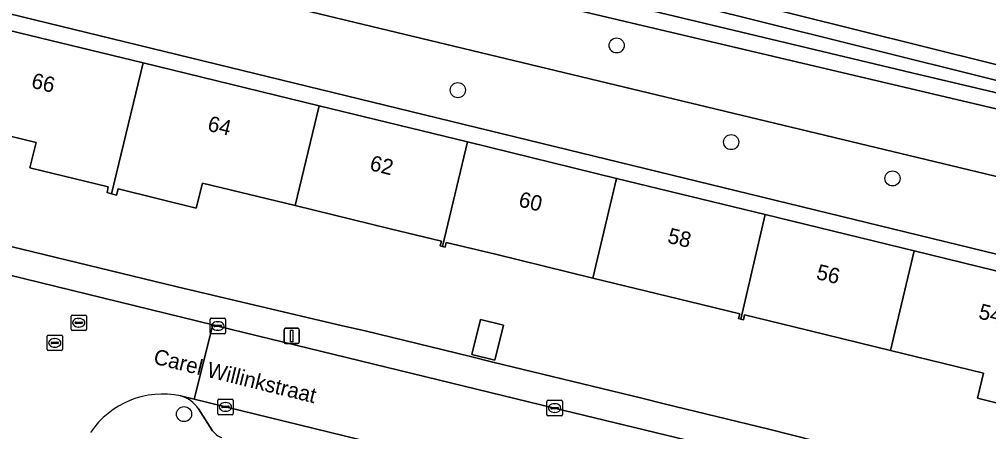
# Model space of a CAD drawing. Extents: x 163266 to 164362, y 381528 to 382286.
# Drawn here: x 163875.1 to 163937.9, y 382217.5 to 382244.3 of the extents above; entities that cross this region are included whole.
import ezdxf

# ---------------------------------------------------------------- set-up
doc = ezdxf.new("R2010")
doc.units = 0
for name, color, linetype in [('IMGEO_Berm_groen', 7, 'Continuous'), ('IMGEO_Boom', 7, 'Continuous'), ('IMGEO_Erf', 7, 'Continuous'), ('IMGEO_Groenvoorziening', 7, 'Continuous'), ('IMGEO_Kolk', 7, 'Continuous'), ('IMGEO_Lichtmast', 7, 'Continuous'), ('IMGEO_Loofbos', 7, 'Continuous'), ('IMGEO_Muur', 7, 'Continuous'), ('IMGEO_Oever', 7, 'Continuous'), ('IMGEO_Openbare_ruimte_label', 7, 'Continuous'), ('IMGEO_Pand', 7, 'Continuous'), ('IMGEO_Pand_nummerreeks', 7, 'Continuous'), ('IMGEO_Parkeervlak_open', 7, 'Continuous'), ('IMGEO_Rijbaan_lokaal_open', 7, 'Continuous'), ('IMGEO_Rioolput', 7, 'Continuous'), ('IMGEO_Voetpad_open', 7, 'Continuous'), ('IMGEO_Waterloop', 7, 'Continuous')]:
    doc.layers.add(name, color=color, linetype=linetype)

msp = doc.modelspace()

# ---------------------------------------------------------------- linework, layer by layer
at = {"layer": 'IMGEO_Berm_groen'}
msp.add_lwpolyline([(163827.813, 382268.559), (163903.688, 382250), (163972.716, 382232.791), (163990.722, 382228.949), (163990.191, 382226.629), (163993.937, 382225.807), (163994.449, 382227.946), (164000, 382226.644), (164034.633, 382218.521)], dxfattribs=at)
at = {"layer": 'IMGEO_Boom'}
for centre in [(163913.84, 382242.566), (163903.551, 382239.667), (163921.265, 382236.298), (163931.72, 382233.943), (163885.808, 382218.656)]:
    msp.add_circle(centre, 0.489, dxfattribs=at)
at = {"layer": 'IMGEO_Erf'}
for points in [[(164000, 382214.018), (163852.505, 382250), (163830.652, 382255.331), (163820.909, 382257.71), (163819.962, 382253.749), (163820.89, 382253.489), (163821.611, 382256.436), (163833.166, 382253.623), (163842.811, 382251.271), (163847.999, 382250), (163852.474, 382248.909), (163862.091, 382246.569), (163871.716, 382244.216), (163883.149, 382241.433), (163894.56, 382238.644), (163904.168, 382236.307), (163913.841, 382233.941), (163923.476, 382231.591), (163933.121, 382229.239), (163944.503, 382226.463)], [(163942.274, 382218.446), (163937.215, 382219.685), (163937.612, 382221.316), (163931.579, 382222.786), (163925.325, 382224.309), (163922.129, 382225.088), (163922.053, 382224.777), (163921.885, 382224.817), (163921.742, 382224.852), (163921.817, 382225.162), (163918.551, 382225.958), (163912.295, 382227.482), (163905.986, 382229.019), (163902.8, 382229.795), (163902.723, 382229.484), (163902.553, 382229.525), (163902.412, 382229.559), (163902.488, 382229.869), (163899.168, 382230.678), (163893.011, 382232.177), (163886.995, 382233.643), (163886.6, 382232.021), (163881.528, 382233.268), (163881.422, 382232.864), (163881.107, 382232.949), (163880.824, 382233.025), (163880.894, 382233.39), (163875.822, 382234.637), (163876.222, 382236.278), (163870.185, 382237.752)], [(163874.578, 382229.533), (163885.354, 382226.906), (163896.086, 382224.391), (163897.546, 382224.049), (163904.364, 382222.388), (163905.821, 382222.033), (163915.471, 382219.682), (163916.928, 382219.327), (163923.701, 382217.677), (163925.155, 382217.309), (163933.327, 382215.242), (163935.971, 382214.573), (163946.731, 382211.952)]]:
    msp.add_lwpolyline(points, dxfattribs=at)
msp.add_lwpolyline([(163904.448, 382222.527), (163905.01, 382224.801), (163906.499, 382224.419), (163905.937, 382222.145)], close=True, dxfattribs=at)
at = {"layer": 'IMGEO_Groenvoorziening'}
for points in [[(163823.874, 382261.74), (163832.907, 382259.458), (163872.239, 382250), (164000, 382219.278), (164136.238, 382186.518), (164142.104, 382184.986)], [(163972.208, 382230.508), (163904.766, 382246.403), (163904.313, 382244.949), (163847.381, 382258.81)]]:
    msp.add_lwpolyline(points, dxfattribs=at)
at = {"layer": 'IMGEO_Kolk'}
for p, q in [((163887.496, 382223.945), (163887.496, 382224.797)), ((163887.571, 382224.871), (163888.423, 382224.871)), ((163887.984, 382224.651), (163888.009, 382224.651)), ((163888.497, 382224.797), (163888.497, 382223.945)), ((163887.755, 382224.365), (163887.755, 382224.377)), ((163888.193, 382224.328), (163887.795, 382224.328)), ((163887.798, 382224.414), (163888.196, 382224.414)), ((163888.007, 382224.091), (163887.982, 382224.091)), ((163888.239, 382224.377), (163888.239, 382224.365)), ((163888.423, 382223.871), (163887.571, 382223.871)), ((163887.991, 382218.693), (163887.991, 382219.545)), ((163888.066, 382219.619), (163888.918, 382219.619)), ((163888.992, 382219.545), (163888.992, 382218.693)), ((163909.397, 382219.549), (163910.249, 382219.549)), ((163888.25, 382219.113), (163888.25, 382219.125)), ((163888.688, 382219.076), (163888.29, 382219.076)), ((163888.293, 382219.162), (163888.691, 382219.162)), ((163888.479, 382219.399), (163888.504, 382219.399)), ((163888.734, 382219.125), (163888.734, 382219.113)), ((163909.322, 382218.623), (163909.322, 382219.475)), ((163909.581, 382219.043), (163909.581, 382219.055)), ((163910.019, 382219.006), (163909.621, 382219.006)), ((163909.624, 382219.092), (163910.022, 382219.092)), ((163909.81, 382219.329), (163909.835, 382219.329)), ((163910.065, 382219.055), (163910.065, 382219.043)), ((163910.323, 382219.475), (163910.323, 382218.623)), ((163888.918, 382218.619), (163888.066, 382218.619)), ((163888.502, 382218.839), (163888.477, 382218.839)), ((163910.249, 382218.549), (163909.397, 382218.549)), ((163909.833, 382218.769), (163909.808, 382218.769))]:
    msp.add_line(p, q, dxfattribs=at)
for points in [[(163887.496, 382223.945), (163887.496, 382224.797)], [(163887.571, 382224.871), (163888.423, 382224.871)], [(163888.497, 382224.797), (163888.497, 382223.945)], [(163888.423, 382223.871), (163887.571, 382223.871)], [(163887.991, 382218.693), (163887.991, 382219.545)], [(163888.066, 382219.619), (163888.918, 382219.619)], [(163888.992, 382219.545), (163888.992, 382218.693)], [(163909.397, 382219.549), (163910.249, 382219.549)], [(163909.322, 382218.623), (163909.322, 382219.475)], [(163910.323, 382219.475), (163910.323, 382218.623)], [(163888.918, 382218.619), (163888.066, 382218.619)], [(163910.249, 382218.549), (163909.397, 382218.549)]]:
    msp.add_lwpolyline(points, dxfattribs=at)
for centre, radius, start, end in [((163887.573, 382224.795), 0.0765, 91.55205, 178.44795), ((163887.573, 382224.795), 0.0765, 91.55205, 178.44795), ((163888.421, 382224.795), 0.0765, 1.55205, 88.44795), ((163888.421, 382224.795), 0.0765, 1.55205, 88.44795), ((163887.573, 382223.947), 0.0765, 181.55205, 268.44795), ((163887.573, 382223.947), 0.0765, 181.55205, 268.44795), ((163887.795, 382224.374), 0.0403, 85.87752, 175.75265), ((163887.792, 382224.364), 0.0366, 178.93798, 274.71019), ((163888.196, 382224.371), 0.043, 264.86636, 352.45326), ((163888.2, 382224.376), 0.0386, 1.73085, 96.63898), ((163888.421, 382223.947), 0.0765, 271.55205, 358.44795), ((163888.421, 382223.947), 0.0765, 271.55205, 358.44795), ((163888.068, 382219.543), 0.0765, 91.55205, 178.44795), ((163888.068, 382219.543), 0.0765, 91.55205, 178.44795), ((163888.916, 382219.543), 0.0765, 1.55205, 88.44795), ((163888.916, 382219.543), 0.0765, 1.55205, 88.44795), ((163909.399, 382219.473), 0.0765, 91.55205, 178.44795), ((163909.399, 382219.473), 0.0765, 91.55205, 178.44795), ((163910.247, 382219.473), 0.0765, 1.55205, 88.44795), ((163910.247, 382219.473), 0.0765, 1.55205, 88.44795), ((163888.29, 382219.122), 0.0403, 85.87752, 175.75265), ((163888.287, 382219.112), 0.0366, 178.93798, 274.71019), ((163888.691, 382219.119), 0.043, 264.86636, 352.45326), ((163888.695, 382219.124), 0.0386, 1.73085, 96.63898), ((163909.621, 382219.052), 0.0403, 85.87752, 175.75265), ((163909.618, 382219.042), 0.0366, 178.93798, 274.71019), ((163910.022, 382219.049), 0.043, 264.86636, 352.45326), ((163910.026, 382219.054), 0.0386, 1.73085, 96.63898), ((163888.068, 382218.695), 0.0765, 181.55205, 268.44795), ((163888.068, 382218.695), 0.0765, 181.55205, 268.44795), ((163888.916, 382218.695), 0.0765, 271.55205, 358.44795), ((163888.916, 382218.695), 0.0765, 271.55205, 358.44795), ((163909.399, 382218.625), 0.0765, 181.55205, 268.44795), ((163909.399, 382218.625), 0.0765, 181.55205, 268.44795), ((163910.247, 382218.625), 0.0765, 271.55205, 358.44795), ((163910.247, 382218.625), 0.0765, 271.55205, 358.44795)]:
    msp.add_arc(centre, radius, start, end, dxfattribs=at)
for centre, major_axis, ratio, start_param, end_param in [((163887.983, 382224.371), (-0.387, 0.002), 0.722429, 4.712389, 7.853982), ((163888.008, 382224.371), (-0.39, 0.002), 0.717154, 1.570796, 4.712389), ((163888.478, 382219.119), (-0.387, 0.002), 0.722429, 4.712389, 7.853982), ((163888.503, 382219.119), (-0.39, 0.002), 0.717154, 1.570796, 4.712389), ((163909.809, 382219.049), (-0.387, 0.002), 0.722429, 4.712389, 7.853982), ((163909.834, 382219.049), (-0.39, 0.002), 0.717154, 1.570796, 4.712389)]:
    msp.add_ellipse(centre, major_axis=major_axis, ratio=ratio, start_param=start_param, end_param=end_param, dxfattribs=at)
at = {"layer": 'IMGEO_Lichtmast'}
for p, q in [((163892.288, 382223.326), (163892.288, 382224.126)), ((163892.288, 382224.126), (163892.288, 382223.326)), ((163892.388, 382224.226), (163893.178, 382224.226)), ((163893.178, 382224.226), (163892.388, 382224.226)), ((163893.278, 382224.126), (163893.278, 382223.326)), ((163893.278, 382223.326), (163893.278, 382224.126)), ((163893.178, 382223.226), (163892.388, 382223.226)), ((163892.388, 382223.226), (163893.178, 382223.226))]:
    msp.add_line(p, q, dxfattribs=at)
msp.add_lwpolyline([(163892.708, 382224.101), (163892.858, 382224.101), (163892.858, 382223.351), (163892.708, 382223.351), (163892.708, 382224.101)], dxfattribs=at)
for centre, start, end in [((163892.388, 382224.126), 90, 180), ((163892.388, 382224.126), 90, 180), ((163893.178, 382224.126), 0, 90), ((163893.178, 382224.126), 360, 90), ((163892.388, 382223.326), 180, 270), ((163892.388, 382223.326), 180, 270), ((163893.178, 382223.326), 270, 0), ((163893.178, 382223.326), 270, 0)]:
    msp.add_arc(centre, 0.1, start, end, dxfattribs=at)
at = {"layer": 'IMGEO_Loofbos'}
for points in [[(164142.104, 382184.986), (164136.238, 382186.518), (164000, 382219.278), (163872.239, 382250), (163832.907, 382259.458), (163823.874, 382261.74)], [(163817.409, 382251.574), (163819.3, 382251.045), (163819.962, 382253.749), (163820.909, 382257.71), (163830.652, 382255.331), (163852.505, 382250), (164000, 382214.018), (164033.312, 382205.891), (164134.264, 382181.264), (164140.582, 382179.712)]]:
    msp.add_lwpolyline(points, dxfattribs=at)
at = {"layer": 'IMGEO_Muur'}
for points in [[(163885.354, 382226.906), (163896.086, 382224.391)], [(163905.821, 382222.033), (163915.471, 382219.682)]]:
    msp.add_lwpolyline(points, dxfattribs=at)
at = {"layer": 'IMGEO_Oever'}
for points in [[(163958.066, 382234.869), (163932.961, 382240.785), (163881.588, 382253.084), (163857.852, 382258.89), (163848.107, 382261.273), (163837.34, 382263.906), (163827.273, 382266.368), (163827.064, 382266.492), (163826.972, 382266.676), (163826.952, 382266.745), (163827.04, 382267.031), (163827.102, 382267.143), (163827.191, 382267.259), (163827.269, 382267.331), (163827.557, 382267.492), (163827.786, 382267.536), (163843.496, 382263.694), (163870.789, 382257.018), (163894.966, 382251.104), (163922.095, 382244.38), (163946.192, 382238.373)], [(163826.892, 382265.432), (163847.869, 382260.302), (163889.989, 382250), (163902.877, 382246.848), (163904.766, 382246.403), (163972.208, 382230.508), (163990.191, 382226.629), (163990.722, 382228.949), (163972.716, 382232.791), (163903.688, 382250)]]:
    msp.add_lwpolyline(points, dxfattribs=at)
at = {"layer": 'IMGEO_Pand'}
for points in [[(163881.107, 382232.949), (163883.149, 382241.433), (163871.716, 382244.216), (163870.185, 382237.752), (163876.222, 382236.278), (163875.822, 382234.637), (163880.894, 382233.39), (163880.824, 382233.025)], [(163881.107, 382232.949), (163881.422, 382232.864), (163881.528, 382233.268), (163886.6, 382232.021), (163886.995, 382233.643), (163893.011, 382232.177), (163894.56, 382238.644), (163883.149, 382241.433)], [(163902.553, 382229.525), (163904.168, 382236.307), (163894.56, 382238.644), (163893.011, 382232.177), (163899.168, 382230.678), (163902.488, 382229.869), (163902.412, 382229.559)], [(163902.553, 382229.525), (163902.723, 382229.484), (163902.8, 382229.795), (163905.986, 382229.019), (163912.295, 382227.482), (163913.841, 382233.941), (163904.168, 382236.307)], [(163923.476, 382231.591), (163913.841, 382233.941), (163912.295, 382227.482), (163918.551, 382225.958), (163921.817, 382225.162), (163921.742, 382224.852), (163921.885, 382224.817)], [(163923.476, 382231.591), (163921.885, 382224.817), (163922.053, 382224.777), (163922.129, 382225.088), (163925.325, 382224.309), (163931.579, 382222.786), (163933.121, 382229.239)], [(163944.503, 382226.463), (163933.121, 382229.239), (163931.579, 382222.786), (163937.612, 382221.316), (163937.215, 382219.685), (163942.274, 382218.446), (163942.186, 382218.058), (163942.491, 382217.983)], [(163904.448, 382222.527), (163905.937, 382222.145), (163906.499, 382224.419), (163905.01, 382224.801)]]:
    msp.add_lwpolyline(points, close=True, dxfattribs=at)
at = {"layer": 'IMGEO_Parkeervlak_open'}
for points in [[(163932.431, 382208.4), (163931.692, 382208.593), (163928.543, 382209.364), (163907.684, 382214.44), (163888.493, 382219.12), (163886.466, 382219.622), (163885.586, 382219.84)], [(163886.734, 382219), (163887.648, 382217.581)]]:
    msp.add_lwpolyline(points, dxfattribs=at)
for centre, radius, start, end in [((163885.051, 382217.905), 2.008, 33.05843, 74.55516), ((163888.589, 382218.242), 1.15, 215.07684, 253.51362)]:
    msp.add_arc(centre, radius, start, end, dxfattribs=at)
at = {"layer": 'IMGEO_Rijbaan_lokaal_open'}
for points in [[(163887.667, 382224.454), (163870.358, 382228.687), (163869.181, 382223.841), (163869.912, 382223.666), (163870.1, 382223.621)], [(163885.586, 382219.84), (163886.466, 382219.622), (163887.667, 382224.454)]]:
    msp.add_lwpolyline(points, dxfattribs=at)
msp.add_lwpolyline([(163886.466, 382219.622), (163888.493, 382219.12), (163907.684, 382214.44), (163928.543, 382209.364), (163931.692, 382208.593), (163932.888, 382213.459), (163930.627, 382214.004), (163909.822, 382219.048), (163887.996, 382224.37), (163887.667, 382224.454)], close=True, dxfattribs=at)
msp.add_arc((163884.436, 382214.312), 5.647, 78.24551, 146.15012, dxfattribs=at)
at = {"layer": 'IMGEO_Rioolput'}
for p, q in [((163878.485, 382224.156), (163878.485, 382225.008)), ((163878.56, 382225.082), (163879.412, 382225.082)), ((163878.744, 382224.576), (163878.744, 382224.588)), ((163879.182, 382224.539), (163878.784, 382224.539)), ((163878.787, 382224.625), (163879.185, 382224.625)), ((163878.973, 382224.862), (163878.998, 382224.862)), ((163879.228, 382224.588), (163879.228, 382224.576)), ((163879.486, 382225.008), (163879.486, 382224.156)), ((163879.412, 382224.082), (163878.56, 382224.082)), ((163878.996, 382224.302), (163878.971, 382224.302)), ((163876.931, 382222.85), (163876.931, 382223.702)), ((163877.006, 382223.776), (163877.858, 382223.776)), ((163877.19, 382223.27), (163877.19, 382223.282)), ((163877.233, 382223.319), (163877.631, 382223.319)), ((163877.419, 382223.556), (163877.444, 382223.556)), ((163877.674, 382223.282), (163877.674, 382223.27)), ((163877.932, 382223.702), (163877.932, 382222.85)), ((163877.858, 382222.776), (163877.006, 382222.776)), ((163877.628, 382223.233), (163877.23, 382223.233)), ((163877.442, 382222.996), (163877.417, 382222.996))]:
    msp.add_line(p, q, dxfattribs=at)
for points in [[(163878.485, 382224.156), (163878.485, 382225.008)], [(163878.56, 382225.082), (163879.412, 382225.082)], [(163879.486, 382225.008), (163879.486, 382224.156)], [(163879.412, 382224.082), (163878.56, 382224.082)], [(163876.931, 382222.85), (163876.931, 382223.702)], [(163877.006, 382223.776), (163877.858, 382223.776)], [(163877.932, 382223.702), (163877.932, 382222.85)], [(163877.858, 382222.776), (163877.006, 382222.776)]]:
    msp.add_lwpolyline(points, dxfattribs=at)
for centre, radius, start, end in [((163878.562, 382225.006), 0.0765, 91.55205, 178.44795), ((163878.562, 382225.006), 0.0765, 91.55205, 178.44795), ((163878.784, 382224.585), 0.0403, 85.87752, 175.75265), ((163878.781, 382224.575), 0.0366, 178.93798, 274.71019), ((163879.185, 382224.582), 0.043, 264.86636, 352.45326), ((163879.189, 382224.587), 0.0386, 1.73085, 96.63898), ((163879.41, 382225.006), 0.0765, 1.55205, 88.44795), ((163879.41, 382225.006), 0.0765, 1.55205, 88.44795), ((163878.562, 382224.158), 0.0765, 181.55205, 268.44795), ((163878.562, 382224.158), 0.0765, 181.55205, 268.44795), ((163879.41, 382224.158), 0.0765, 271.55205, 358.44795), ((163879.41, 382224.158), 0.0765, 271.55205, 358.44795), ((163877.008, 382223.7), 0.0765, 91.55205, 178.44795), ((163877.008, 382223.7), 0.0765, 91.55205, 178.44795), ((163877.23, 382223.279), 0.0403, 85.87752, 175.75265), ((163877.227, 382223.269), 0.0366, 178.93798, 274.71019), ((163877.631, 382223.276), 0.043, 264.86636, 352.45326), ((163877.635, 382223.281), 0.0386, 1.73085, 96.63898), ((163877.856, 382223.7), 0.0765, 1.55205, 88.44795), ((163877.856, 382223.7), 0.0765, 1.55205, 88.44795), ((163877.008, 382222.852), 0.0765, 181.55205, 268.44795), ((163877.008, 382222.852), 0.0765, 181.55205, 268.44795), ((163877.856, 382222.852), 0.0765, 271.55205, 358.44795), ((163877.856, 382222.852), 0.0765, 271.55205, 358.44795)]:
    msp.add_arc(centre, radius, start, end, dxfattribs=at)
for centre, major_axis, ratio, start_param, end_param in [((163878.972, 382224.582), (-0.387, 0.002), 0.722429, 4.712389, 7.853982), ((163878.997, 382224.582), (-0.39, 0.002), 0.717154, 1.570796, 4.712389), ((163877.418, 382223.276), (-0.387, 0.002), 0.722429, 4.712389, 7.853982), ((163877.443, 382223.276), (-0.39, 0.002), 0.717154, 1.570796, 4.712389)]:
    msp.add_ellipse(centre, major_axis=major_axis, ratio=ratio, start_param=start_param, end_param=end_param, dxfattribs=at)
at = {"layer": 'IMGEO_Voetpad_open'}
for points in [[(163870.358, 382228.687), (163887.667, 382224.454), (163887.996, 382224.37), (163909.822, 382219.048), (163930.627, 382214.004), (163932.888, 382213.459), (163933.327, 382215.242), (163925.155, 382217.309), (163923.701, 382217.677), (163916.928, 382219.327), (163915.471, 382219.682), (163905.821, 382222.033), (163904.364, 382222.388), (163897.546, 382224.049), (163896.086, 382224.391), (163885.354, 382226.906), (163874.578, 382229.533)], [(163887.648, 382217.581), (163886.734, 382219)]]:
    msp.add_lwpolyline(points, dxfattribs=at)
for centre, radius, start, end in [((163884.436, 382214.312), 5.647, 78.24551, 146.15012), ((163885.051, 382217.905), 2.008, 33.05843, 74.55516), ((163888.589, 382218.242), 1.15, 215.07684, 253.51362)]:
    msp.add_arc(centre, radius, start, end, dxfattribs=at)
at = {"layer": 'IMGEO_Waterloop'}
msp.add_lwpolyline([(163946.192, 382238.373), (163922.095, 382244.38), (163894.966, 382251.104), (163870.789, 382257.018), (163843.496, 382263.694), (163827.786, 382267.536), (163827.557, 382267.492), (163827.269, 382267.331), (163827.191, 382267.259), (163827.102, 382267.143), (163827.04, 382267.031), (163826.952, 382266.745), (163826.972, 382266.676), (163827.064, 382266.492), (163827.273, 382266.368), (163837.34, 382263.906), (163848.107, 382261.273), (163857.852, 382258.89), (163881.588, 382253.084), (163932.961, 382240.785), (163958.066, 382234.869)], dxfattribs=at)

# ---------------------------------------------------------------- texts
at = {"layer": 'IMGEO_Openbare_ruimte_label'}
msp.add_text('Carel Willinkstraat', height=1, rotation=346.11658, dxfattribs=at).set_placement((163883.767, 382221.939))
at = {"layer": 'IMGEO_Pand_nummerreeks'}
for s, rotation, p in [('66', 346.29442, (163875.853, 382239.837)), ('64', 346.295, (163887.275, 382237.051)), ('62', 346.294, (163897.781, 382234.489)), ('60', 346.29031, (163907.428, 382232.136)), ('58', 346.29304, (163917.082, 382229.781)), ('56', 346.2955, (163926.719, 382227.431)), ('54', 346.29466, (163937.233, 382224.867))]:
    msp.add_text(s, height=1, rotation=rotation, dxfattribs=at).set_placement(p)

doc.saveas('drawing.dxf')
